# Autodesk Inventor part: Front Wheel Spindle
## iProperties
Shininess: 70.0
Angle Display Precision: 2
Document Length Units: 11269
Document Angle Units: 11279
Document Time Units: 11290
Document Mass Units: 11283
Document Length Units Precision: 3
Document Angle Units Precision: 2
Compacted: True
Created: 2001-08
Part Number: Front Wheel Spindle
Document SubType Name: Modeling
Designer: Martin Budgell
Density: 0.0
Volumn: 0.0
Area: 0.0
PropertySet Name: Model Information
Control State: 0
Master: False
Checked Out: False
Author: Martin Budgell
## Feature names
1. Extrusion1
2. Chamfer1
3. Extrusion2
4. Extrusion3
5. Extrusion4
6. Extrusion5
7. Chamfer2
